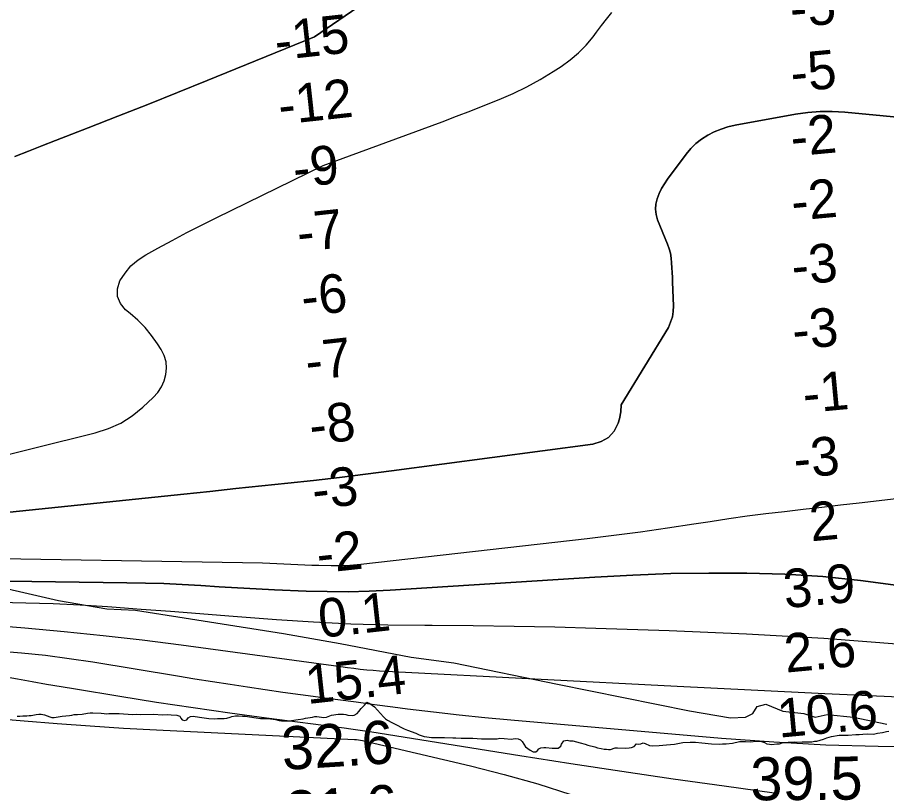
# Model space of a CAD drawing. Extents: x 3245246 to 3283090, y 806824 to 832173.
# Drawn here: x 3262284 to 3263634, y 818874 to 820069 of the extents above; entities that cross this region are included whole.
import ezdxf

# ---------------------------------------------------------------- set-up
doc = ezdxf.new("R2010")
doc.units = 0
for name, color, linetype in [('V-RIVR-EDGE', 7, 'Continuous'), ('V-RIVR-RANG', 7, 'Continuous'), ('V-SITE-VEGE', 7, 'Continuous'), ('V-TOPO-DPTH', 7, 'Continuous'), ('V-TOPO-MAJR', 7, 'Continuous'), ('V-TOPO-MINR', 7, 'Continuous'), ('V-TOPO-WATR', 7, 'Continuous')]:
    doc.layers.add(name, color=color, linetype=linetype)

msp = doc.modelspace()

# ---------------------------------------------------------------- linework, layer by layer
at = {"layer": 'V-RIVR-EDGE'}
msp.add_lwpolyline([(3262215.1, 819194.1), (3262348, 819163.3), (3262423.2, 819150.5), (3262467.5, 819148.2), (3262697.3, 819112), (3262785.5, 819096.6), (3262895.5, 819075.4), (3262961.9, 819066.6), (3263122.7, 819033.6), (3263328.2, 818992.2), (3263391.6, 818981.2), (3263415.1, 818982.4), (3263426.4, 818988.1), (3263433, 818998.9), (3263446.5, 819002.4), (3263472.9, 818991.4), (3263505.5, 818987.9), (3263522.9, 818982.2), (3263542, 818986.5), (3263582.9, 818982), (3263634.6, 818971.5)], dxfattribs=at)
at = {"layer": 'V-SITE-VEGE'}
for points in [[(3262337.6, 818981.8), (3262341.3, 818981.5), (3262353.6, 818983.5), (3262365.1, 818984.6), (3262368.7, 818985.5), (3262372.4, 818986.1), (3262377.3, 818986.4), (3262384.7, 818987.1), (3262393.1, 818988.4), (3262397.2, 818988.7), (3262401.3, 818988.7), (3262414, 818988.4), (3262418.9, 818988.1), (3262422.8, 818987.5), (3262425.9, 818988), (3262441.9, 818988.1), (3262462.8, 818986.3), (3262469.8, 818987), (3262476, 818986.5), (3262494.8, 818986.7), (3262509.8, 818986), (3262517.2, 818986.1), (3262522.7, 818986), (3262531.8, 818985.3), (3262536.1, 818983.7), (3262538, 818980.8), (3262540, 818978.2), (3262543.7, 818977), (3262547, 818978.1), (3262549.2, 818981.2), (3262552.9, 818983.2), (3262557, 818983.7), (3262566.7, 818982.4), (3262581.2, 818979.9), (3262589.9, 818979.6), (3262594.8, 818980), (3262599.5, 818979.9), (3262605.4, 818980.1), (3262609.1, 818980.6), (3262614.4, 818982.1), (3262617.3, 818983.3), (3262622.6, 818984.4), (3262627.7, 818984.1), (3262633.9, 818983.9), (3262637.8, 818983.6), (3262655, 818980.9), (3262661.6, 818980.2), (3262673.7, 818980.3), (3262685, 818978.6), (3262690.4, 818977.2), (3262694.1, 818976.6), (3262700.2, 818976.3), (3262706.6, 818976.4), (3262709.6, 818976.8), (3262719.9, 818978.8), (3262727.9, 818979.7), (3262731.3, 818980.5), (3262735, 818981.2), (3262742.2, 818982.1), (3262746.1, 818983), (3262749.1, 818983.2), (3262760, 818981.9), (3262763.9, 818982.1), (3262769.2, 818984), (3262772.1, 818985.3), (3262782.5, 818987.1), (3262790.7, 818986.7), (3262794.2, 818986.2), (3262797.5, 818985.4), (3262803.9, 818984.6), (3262807.2, 818985.1), (3262812, 818988), (3262814.3, 818991.1), (3262818.1, 818995.7), (3262823.4, 819001), (3262825.8, 819004.1), (3262827, 819005.3), (3262831.2, 819003.6), (3262838.7, 818998.1), (3262848.2, 818987.8), (3262852.6, 818982.7), (3262855.9, 818979.5), (3262858.8, 818977.6), (3262865.6, 818973.8), (3262869.9, 818972), (3262885, 818964.2), (3262889.9, 818962), (3262902.9, 818957.2), (3262908.1, 818955), (3262915.7, 818952.4), (3262920.2, 818951.5), (3262927, 818950.5), (3262947.5, 818950.5), (3262960.4, 818950.3), (3262964.9, 818950.1), (3262973.5, 818949.4), (3262986.5, 818949.7), (3262991.6, 818949.6), (3263004.9, 818948.5), (3263029.1, 818948.6), (3263033.5, 818949.4)], [(3262283.7, 818983.7), (3262288, 818983.8), (3262292.5, 818984.2), (3262298.8, 818984.3), (3262302.1, 818984.7), (3262305.6, 818985), (3262313.4, 818986.1), (3262317.5, 818987), (3262320.9, 818987), (3262325.9, 818985.6), (3262334.3, 818982.6), (3262337.6, 818981.8)], [(3263033.5, 818949.4), (3263040.1, 818949.3), (3263051, 818948.2), (3263054.3, 818948.5), (3263058.3, 818949.1), (3263062, 818948.6), (3263065.5, 818947.2), (3263068.2, 818944.3), (3263073.3, 818936), (3263080.5, 818930.7), (3263085.4, 818928.5), (3263089.3, 818928.4), (3263092, 818930.2), (3263094.2, 818933.1), (3263097.1, 818934.8), (3263101.8, 818935.3), (3263104.8, 818935.1), (3263114.5, 818933.8), (3263120.7, 818933.8), (3263123.9, 818934.1), (3263128, 818937), (3263129.4, 818940.3), (3263133, 818945.3), (3263137.7, 818946.3), (3263142.1, 818945.6), (3263146.8, 818945.2), (3263158.1, 818942.1), (3263166.1, 818940.1), (3263170, 818938.9), (3263180.7, 818936.2), (3263185, 818934.8), (3263190.6, 818933.4), (3263195.3, 818932.6), (3263198.8, 818932.5), (3263201.9, 818932.1), (3263205.2, 818932.1), (3263212.5, 818934.5), (3263216, 818934.7), (3263229.3, 818934.2), (3263234, 818934.3), (3263237.7, 818935.2), (3263241.8, 818936.6), (3263245.5, 818940.6), (3263249.2, 818940.4), (3263252.6, 818940.7), (3263256.1, 818942.1), (3263259.2, 818941.3), (3263266, 818938.1), (3263270.3, 818937.8), (3263280.6, 818938.1), (3263292.4, 818939), (3263304.7, 818940.4), (3263317.4, 818942.6), (3263329.1, 818943.4), (3263337.5, 818943.5), (3263347.3, 818942.5), (3263362.3, 818940.9), (3263375.1, 818940), (3263379.2, 818940.8), (3263385.1, 818940.9), (3263394.7, 818941.6), (3263405.4, 818944.4), (3263414.8, 818944.3), (3263422, 818943.8), (3263432.2, 818944.7), (3263435.9, 818944.8), (3263440, 818944.4), (3263444.3, 818943), (3263448.3, 818941), (3263452.2, 818940), (3263455.7, 818939.9), (3263463.6, 818940.8), (3263467.5, 818941), (3263472, 818942.1), (3263481.4, 818943.4), (3263487.2, 818943.5), (3263490.9, 818943.7), (3263495.6, 818943.6), (3263503.2, 818944.1), (3263507.7, 818944.1), (3263514.5, 818943.8), (3263517.9, 818943.8), (3263522, 818944.7), (3263525.5, 818944.9), (3263536.1, 818947.9), (3263541.5, 818950), (3263548.6, 818952.2), (3263560.5, 818954), (3263564.6, 818954.2), (3263574.6, 818954.1), (3263586.5, 818955.3), (3263591.6, 818955.3), (3263597.2, 818955.8), (3263604.8, 818956.1), (3263613.8, 818956), (3263619.9, 818957.1), (3263627.7, 818958.2), (3263634, 818959.7), (3263637.7, 818960.4)]]:
    msp.add_lwpolyline(points, dxfattribs=at)
at = {"layer": 'V-TOPO-DPTH'}
for points in [[(3262280.2, 819853.2), (3262301.2, 819861.4), (3262322.2, 819869.6), (3262343.2, 819877.8), (3262394, 819897.6), (3262440.3, 819915.8), (3262486.6, 819934.1), (3262532.8, 819952.6), (3262579, 819971.2), (3262745.4, 820038.8), (3262868.8, 820124)], [(3262868.8, 820124), (3262745.4, 820038.8), (3262579, 819971.2), (3262532.8, 819952.6), (3262486.6, 819934.1), (3262440.3, 819915.8), (3262394, 819897.6), (3262343.2, 819877.8), (3262322.2, 819869.6), (3262301.2, 819861.4), (3262280.2, 819853.2)], [(3263758.6, 819904.1), (3263569, 819922.1), (3263549.8, 819923.1), (3263530.7, 819923.1), (3263511.6, 819921.5), (3263492.6, 819918.8), (3263398.8, 819901.7), (3263387.7, 819899.1), (3263376.9, 819895.8), (3263366.4, 819891.4), (3263356.2, 819886.4), (3263346.7, 819880.2), (3263337.8, 819873.3), (3263329.9, 819865.3), (3263322.6, 819856.7), (3263293.9, 819817.9), (3263289, 819810.8), (3263284.6, 819803.3), (3263281, 819795.5), (3263277.7, 819787.5), (3263275.9, 819779.3), (3263275.2, 819771.1), (3263276.2, 819762.9), (3263278.5, 819754.8), (3263293.7, 819716.9), (3263296.2, 819709.8), (3263298.2, 819702.7), (3263299.4, 819695.3), (3263300.2, 819687.9), (3263300.6, 819680.4), (3263301, 819672.8), (3263301.3, 819665.3), (3263301.6, 819657.8), (3263303, 819621.1), (3263302.6, 819612.4), (3263301.3, 819603.8), (3263298.7, 819595.6), (3263295.3, 819587.5), (3263222, 819467.6), (3263221.5, 819456.7), (3263219.4, 819445.8), (3263217.2, 819438.9), (3263210.7, 819426.7), (3263202.2, 819416.8), (3263190.9, 819410.2), (3263177.7, 819406), (3262864.9, 819364.7), (3262824.7, 819359.5), (3262784.5, 819354.6), (3262744.2, 819350), (3262703.9, 819345.6), (3262663.6, 819341.4), (3262623.3, 819337.2), (3262582.9, 819332.9), (3262542.6, 819328.7), (3262196.8, 819292.6)], [(3262196.8, 819292.6), (3262542.6, 819328.7), (3262582.9, 819332.9), (3262623.3, 819337.2), (3262663.6, 819341.4), (3262703.9, 819345.6), (3262744.2, 819350), (3262784.5, 819354.6), (3262824.7, 819359.5), (3262864.9, 819364.7), (3263177.7, 819406), (3263190.9, 819410.2), (3263202.2, 819416.8), (3263210.7, 819426.7), (3263217.2, 819438.9), (3263219.4, 819445.8), (3263221.5, 819456.7), (3263222, 819467.6), (3263295.3, 819587.5), (3263298.7, 819595.6), (3263301.3, 819603.8), (3263302.6, 819612.4), (3263303, 819621.1), (3263301.6, 819657.8), (3263301.3, 819665.3), (3263301, 819672.8), (3263300.6, 819680.4), (3263300.2, 819687.9), (3263299.4, 819695.3), (3263298.2, 819702.7), (3263296.2, 819709.8), (3263293.7, 819716.9), (3263278.5, 819754.8), (3263276.2, 819762.9), (3263275.2, 819771.1), (3263275.9, 819779.3), (3263277.7, 819787.5), (3263281, 819795.5), (3263284.6, 819803.3), (3263289, 819810.8), (3263293.9, 819817.9), (3263322.6, 819856.7), (3263329.9, 819865.3), (3263337.8, 819873.3), (3263346.7, 819880.2), (3263356.2, 819886.4), (3263366.4, 819891.4), (3263376.9, 819895.8), (3263387.7, 819899.1), (3263398.8, 819901.7), (3263492.6, 819918.8), (3263511.6, 819921.5), (3263530.7, 819923.1), (3263549.8, 819923.1), (3263569, 819922.1), (3263758.6, 819904.1)], [(3263652.2, 819186.8), (3263593.7, 819194.5), (3263535, 819200.5), (3263476.1, 819204.1), (3263417.1, 819206), (3263358, 819206), (3263298.9, 819205.2), (3263239.8, 819202.9), (3263180.8, 819199.8), (3262862.8, 819179.4), (3262830.3, 819177.9), (3262797.8, 819177), (3262765.3, 819177.2), (3262732.7, 819178.1), (3262683.3, 819180.2), (3262654.7, 819181.6), (3262626.1, 819183.1), (3262597.4, 819184.8), (3262568.8, 819186.6), (3262540.2, 819188.2), (3262511.6, 819189.6), (3262482.9, 819190.5), (3262454.2, 819191.1), (3262232, 819194.1)], [(3263652.2, 819186.8), (3263593.7, 819194.5), (3263535, 819200.5), (3263476.1, 819204.1), (3263417.1, 819206), (3263358, 819206), (3263298.9, 819205.2), (3263239.8, 819202.9), (3263180.8, 819199.8), (3262862.8, 819179.4), (3262830.3, 819177.9), (3262797.8, 819177), (3262765.3, 819177.2), (3262732.7, 819178.1), (3262683.3, 819180.2), (3262654.7, 819181.6), (3262626.1, 819183.1), (3262597.4, 819184.8), (3262568.8, 819186.6), (3262540.2, 819188.2), (3262511.6, 819189.6), (3262482.9, 819190.5), (3262454.2, 819191.1), (3262232, 819194.1)], [(3262174.1, 819130.6), (3262295.8, 819120.8), (3262356.5, 819115.4), (3262417.3, 819109.3), (3262477.9, 819102.2), (3262538.4, 819094.5), (3262786.6, 819060.7), (3262796.6, 819059.3), (3262806.6, 819058.1), (3262816.7, 819057), (3262826.7, 819055.9), (3262836.7, 819055), (3262846.7, 819054.2), (3262856.8, 819053.5), (3262866.9, 819052.9), (3263308.8, 819030.5), (3263423.6, 819024.8), (3263538.4, 819019.2), (3263653.2, 819013.7)]]:
    msp.add_lwpolyline(points, dxfattribs=at)
at = {"layer": 'V-TOPO-MAJR'}
msp.add_lwpolyline([(3262238, 818981.2), (3262294.4, 818976.3), (3262345.7, 818972.2), (3262397.1, 818968.5), (3262448.6, 818965.3), (3262500, 818962.5), (3262807.8, 818947.5), (3262810.9, 818947.3), (3262814, 818946.9), (3262817.1, 818946.4), (3262820.2, 818945.8), (3262987.9, 818906.7), (3263040.3, 818893.3), (3263092.4, 818878.6), (3263143.9, 818861.9)], dxfattribs=at)
at = {"layer": 'V-TOPO-MINR'}
for points in [[(3262280.2, 819853.2), (3262301.2, 819861.4), (3262322.2, 819869.6), (3262343.2, 819877.8), (3262394, 819897.6), (3262440.3, 819915.8), (3262486.6, 819934.1), (3262532.8, 819952.6), (3262579, 819971.2), (3262745.4, 820038.8), (3262868.8, 820124)], [(3262215.1, 819376.8), (3262405.1, 819423.8), (3262425.3, 819430.5), (3262444.6, 819439.1), (3262462.3, 819450.5), (3262478.9, 819463.8), (3262495.1, 819479), (3262502, 819486.7), (3262507.7, 819495.1), (3262511.8, 819504.4), (3262514.8, 819514.3), (3262515.6, 819524.5), (3262515, 819534.4), (3262512, 819543.9), (3262507.5, 819553.1), (3262501.6, 819562.2), (3262492.4, 819575.2), (3262482.3, 819587.5), (3262471.1, 819598.8), (3262459.1, 819609.3), (3262452.2, 819614.8), (3262444.1, 819624.9), (3262439.4, 819635.7), (3262439.6, 819647.4), (3262443.1, 819659.8), (3262451.2, 819672), (3262460.5, 819683.1), (3262471.5, 819692.4), (3262483.7, 819700.6), (3262502.2, 819710.7), (3262524.7, 819722.8), (3262547.2, 819734.8), (3262570, 819746.4), (3262592.8, 819757.8), (3262759, 819839.2), (3262943.8, 819907.2), (3262966, 819915.5), (3262988.2, 819923.9), (3263010.3, 819932.6), (3263032.4, 819941.4), (3263054.1, 819950.9), (3263075.4, 819961.1), (3263096.1, 819972.6), (3263116.3, 819984.9), (3263128.6, 819992.9), (3263142.5, 820003), (3263155.5, 820013.9), (3263167.3, 820026.1), (3263178.2, 820039.2), (3263183.4, 820046.1), (3263191.2, 820056.4), (3263199.2, 820066.6), (3263207.3, 820076.7)], [(3262196.8, 819292.6), (3262542.6, 819328.7), (3262582.9, 819332.9), (3262623.3, 819337.2), (3262663.6, 819341.4), (3262703.9, 819345.6), (3262744.2, 819350), (3262784.5, 819354.6), (3262824.7, 819359.5), (3262864.9, 819364.7), (3263177.7, 819406), (3263190.9, 819410.2), (3263202.2, 819416.8), (3263210.7, 819426.7), (3263217.2, 819438.9), (3263219.4, 819445.8), (3263221.5, 819456.7), (3263222, 819467.6), (3263295.3, 819587.5), (3263298.7, 819595.6), (3263301.3, 819603.8), (3263302.6, 819612.4), (3263303, 819621.1), (3263301.6, 819657.8), (3263301.3, 819665.3), (3263301, 819672.8), (3263300.6, 819680.4), (3263300.2, 819687.9), (3263299.4, 819695.3), (3263298.2, 819702.7), (3263296.2, 819709.8), (3263293.7, 819716.9), (3263278.5, 819754.8), (3263276.2, 819762.9), (3263275.2, 819771.1), (3263275.9, 819779.3), (3263277.7, 819787.5), (3263281, 819795.5), (3263284.6, 819803.3), (3263289, 819810.8), (3263293.9, 819817.9), (3263322.6, 819856.7), (3263329.9, 819865.3), (3263337.8, 819873.3), (3263346.7, 819880.2), (3263356.2, 819886.4), (3263366.4, 819891.4), (3263376.9, 819895.8), (3263387.7, 819899.1), (3263398.8, 819901.7), (3263492.6, 819918.8), (3263511.6, 819921.5), (3263530.7, 819923.1), (3263549.8, 819923.1), (3263569, 819922.1), (3263758.6, 819904.1)], [(3262163.6, 819230.1), (3262665, 819221.8), (3262675.9, 819221.5), (3262686.8, 819221.1), (3262697.7, 819220.6), (3262708.6, 819220), (3262719.5, 819219.4), (3262730.4, 819218.9), (3262741.3, 819218.4), (3262752.2, 819218.1), (3262771.5, 819217.6), (3262783, 819217.6), (3262794.6, 819217.8), (3262806.2, 819218.6), (3262817.7, 819219.7), (3263169.1, 819259.8), (3263210.6, 819264.8), (3263252.1, 819270.2), (3263293.6, 819276.1), (3263334.9, 819282.4), (3263359.9, 819286.3), (3263388.8, 819290.7), (3263417.7, 819294.8), (3263446.7, 819298.5), (3263475.7, 819301.9), (3263504.7, 819305.2), (3263533.7, 819308.6), (3263562.7, 819311.9), (3263591.7, 819315.3), (3263794.6, 819339)], [(3262255.2, 819160.8), (3262297.4, 819160), (3262339.6, 819158.6), (3262381.8, 819156.5), (3262423.9, 819153.9), (3262430.7, 819153.4), (3262476.2, 819150.1), (3262521.7, 819146.7), (3262567.2, 819143.3), (3262612.7, 819139.8), (3262686.5, 819134), (3262744, 819130.2), (3262801.7, 819127.3), (3262859.3, 819125.7), (3262917, 819124.9), (3262928.5, 819124.9), (3262992, 819124.5), (3263055.4, 819123.8), (3263118.9, 819122.4), (3263182.3, 819120.6), (3263296.2, 819116.8), (3263416.5, 819111.6), (3263536.6, 819104.9), (3263656.6, 819095.7)], [(3262174.1, 819130.6), (3262295.8, 819120.8), (3262356.5, 819115.4), (3262417.3, 819109.3), (3262477.9, 819102.2), (3262538.4, 819094.5), (3262786.6, 819060.7), (3262796.6, 819059.3), (3262806.6, 819058.1), (3262816.7, 819057), (3262826.7, 819055.9), (3262836.7, 819055), (3262846.7, 819054.2), (3262856.8, 819053.5), (3262866.9, 819052.9), (3263308.8, 819030.5), (3263423.6, 819024.8), (3263538.4, 819019.2), (3263653.2, 819013.7)], [(3262253.4, 819085.1), (3262290.5, 819082), (3262327.6, 819078.3), (3262364.5, 819073.5), (3262401.4, 819068), (3262532.5, 819046.4), (3262559.8, 819041.9), (3262587.1, 819037.6), (3262614.4, 819033.3), (3262641.7, 819029.1), (3262669, 819025.1), (3262696.4, 819021.1), (3262723.7, 819017.3), (3262751.1, 819013.6), (3262753.3, 819013.4), (3262781.7, 819009.6), (3262810.2, 819005.9), (3262838.7, 819002.1), (3262867.1, 818998.4), (3262890.1, 818995.3), (3262930.1, 818990.3), (3262970.1, 818985.7), (3263010.2, 818981.6), (3263050.3, 818977.8), (3263377.6, 818949.6), (3263458.7, 818943.7), (3263539.9, 818939.2), (3263621.2, 818937), (3263702.5, 818936.2)], [(3262266.7, 819044.7), (3262284.3, 819041.6), (3262306.8, 819037.6), (3262329.3, 819033.7), (3262351.9, 819029.8), (3262374.5, 819026.1), (3262443.1, 819014.7), (3262500, 819005.7), (3262557, 818997), (3262614.1, 818988.9), (3262671.2, 818981.2), (3262791.4, 818965.6), (3262802.2, 818964.1), (3262813, 818962.6), (3262823.8, 818961), (3262834.6, 818959.3), (3263064.2, 818922.8), (3263143.6, 818910.4), (3263223, 818898.3), (3263302.5, 818886.6), (3263382, 818875.3), (3263459.6, 818864.5)]]:
    msp.add_lwpolyline(points, dxfattribs=at)
at = {"layer": 'V-TOPO-WATR'}
msp.add_lwpolyline([(3262232, 819194.1), (3262454.2, 819191.1), (3262482.9, 819190.5), (3262511.6, 819189.6), (3262540.2, 819188.2), (3262568.8, 819186.6), (3262597.4, 819184.8), (3262626.1, 819183.1), (3262654.7, 819181.6), (3262683.3, 819180.2), (3262732.7, 819178.1), (3262765.3, 819177.2), (3262797.8, 819177), (3262830.3, 819177.9), (3262862.8, 819179.4), (3263180.8, 819199.8), (3263239.8, 819202.9), (3263298.9, 819205.2), (3263358, 819206), (3263417.1, 819206), (3263476.1, 819204.1), (3263535, 819200.5), (3263593.7, 819194.5), (3263652.2, 819186.8)], dxfattribs=at)

# ---------------------------------------------------------------- texts
at = {"layer": 'V-RIVR-RANG'}
for s, height, rotation, p in [('-5', 60, 5.3811, (3263486.4, 820053.1)), ('-15', 60, 6.2843, (3262686.6, 820002.3)), ('-5', 60, 5.3811, (3263487.4, 819953.1)), ('-12', 60, 6.2843, (3262692.2, 819902.4)), ('-2', 60, 5.3811, (3263487.5, 819853)), ('-9', 60, 6.2843, (3262715, 819804.4)), ('-2', 60, 5.3811, (3263488.5, 819753)), ('-7', 60, 6.2843, (3262721.3, 819704.6)), ('-3', 60, 5.3811, (3263489, 819652.9)), ('-6', 60, 6.2843, (3262727.9, 819604.8)), ('-3', 60, 5.3811, (3263490.1, 819552.9)), ('-7', 60, 6.2843, (3262734.4, 819505)), ('-1', 60, 5.3811, (3263506.4, 819454.4)), ('-8', 60, 6.2843, (3262740.5, 819405.2)), ('-3', 60, 5.3811, (3263492.1, 819353)), ('-3', 60, 6.2843, (3262744.8, 819305.1)), ('2', 60, 5.3811, (3263517.1, 819255.2)), ('-2', 60, 6.2843, (3262751.8, 819205.4)), ('3.9', 60, 5.3811, (3263476.5, 819151.3)), ('0.1', 60, 6.2843, (3262754.8, 819105.2)), ('2.6', 60, 5.3811, (3263477.8, 819051.3)), ('15.4', 60, 6.2843, (3262734.6, 819002.5)), ('10.6', 60, 5.3811, (3263467, 818950.2)), ('32.6', 67, 3.6283, (3262696.3, 818899.9)), ('39.5', 67, 0.4383, (3263422.7, 818852.9)), ('31.6', 67, 3.6283, (3262702.9, 818800.1))]:
    msp.add_text(s, height=height, rotation=rotation, dxfattribs=at).set_placement(p)

doc.saveas('drawing.dxf')
